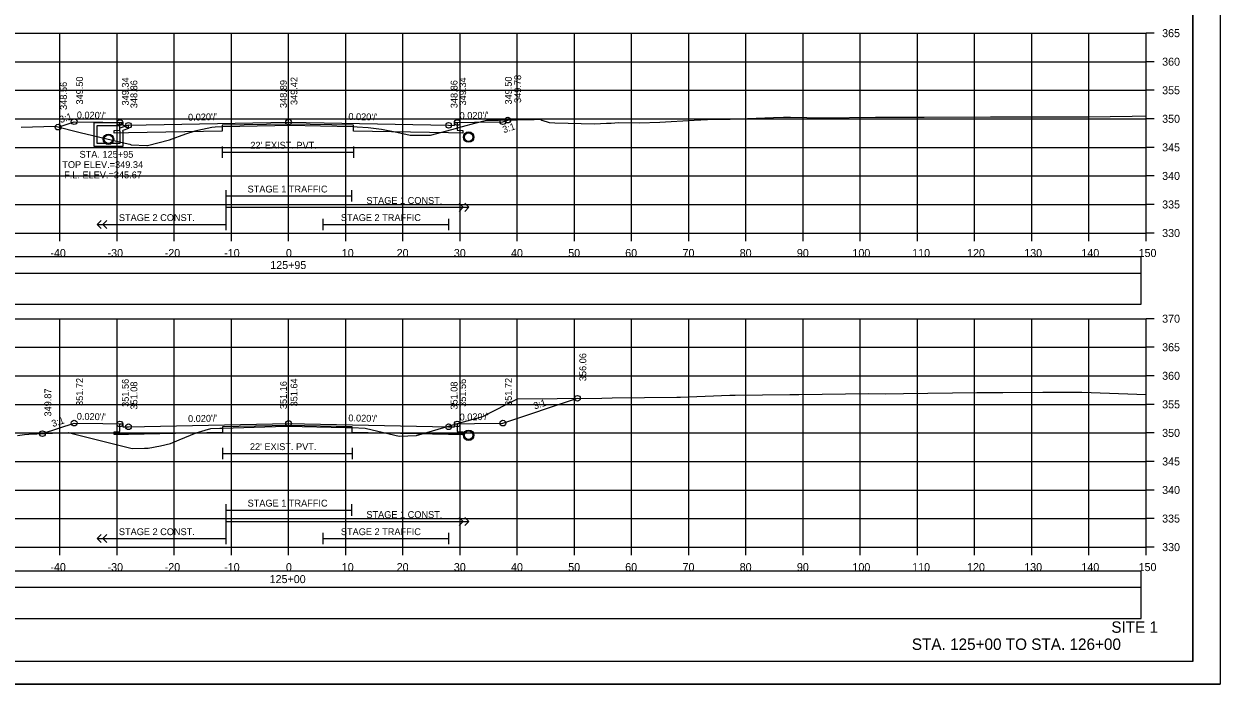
# Model space of a CAD drawing. Extents: x 1368122 to 1710785, y 373130 to 557566.
# Drawn here: x 1368642.6 to 1368851.8, y 376543.7 to 376659.3 of the extents above; entities that cross this region are included whole.
import ezdxf

# ---------------------------------------------------------------- set-up
doc = ezdxf.new("R2010")
doc.units = 0
for name, color, linetype in [('R_Alt Surface', 7, 'Continuous'), ('R_Axis', 7, 'Continuous'), ('R_Axis Annot', 7, 'Continuous'), ('R_Border', 7, 'Continuous'), ('R_Draft', 7, 'Continuous'), ('R_Exist Surface', 7, 'Continuous'), ('R_Fin Surface', 7, 'Continuous'), ('R_Grid', 7, 'Continuous'), ('R_No Plot', 7, 'Continuous'), ('R_Striping', 7, 'Continuous'), ('R_Water', 7, 'Continuous'), ('R_Water Annot', 7, 'Continuous'), ('R_Xsect Elev', 7, 'Continuous'), ('R_Xsect Slope', 7, 'Continuous')]:
    doc.layers.add(name, color=color, linetype=linetype)

msp = doc.modelspace()

# ---------------------------------------------------------------- linework, layer by layer
for points in [[(1368539.73, 376610.24), (1368838.03, 376610.24), (1368838.03, 376615.65), (1368539.73, 376615.65)], [(1368539.73, 376555.24), (1368838.03, 376555.24), (1368838.03, 376560.65), (1368539.73, 376560.65)]]:
    msp.add_lwpolyline(points, close=True)
at = {"layer": 'R_Alt Surface'}
for points in [[(1368718.38, 376642.06), (1368718.38, 376640.72), (1368719.38, 376640.7), (1368719.38, 376640.2), (1368716.88, 376640.25), (1368700.23, 376640.58), (1368700.23, 376641.58), (1368688.88, 376641.81), (1368677.25, 376641.58), (1368677.25, 376640.58), (1368660.88, 376640.25), (1368658.38, 376640.2), (1368658.38, 376640.7), (1368659.38, 376640.72), (1368659.38, 376642.06)], [(1368677.25, 376637.89), (1368677.25, 376635.89)], [(1368677.25, 376636.89), (1368700.23, 376636.89)], [(1368700.23, 376637.89), (1368700.23, 376635.89)], [(1368718.38, 376589.28), (1368718.38, 376587.94), (1368719.38, 376587.92), (1368719.38, 376587.42), (1368716.88, 376587.47), (1368699.98, 376587.81), (1368699.98, 376588.81), (1368688.88, 376589.03), (1368677.35, 376588.8), (1368677.35, 376587.8), (1368660.88, 376587.47), (1368658.38, 376587.42), (1368658.38, 376587.92), (1368659.38, 376587.94), (1368659.38, 376589.28)], [(1368677.35, 376585.11), (1368677.35, 376583.11)], [(1368677.35, 376584.11), (1368699.98, 376584.11)], [(1368699.98, 376585.11), (1368699.98, 376583.11)]]:
    msp.add_lwpolyline(points, dxfattribs=at)
for points in [[(1368539.73, 376615.71), (1368838.03, 376615.71), (1368838.03, 376618.53), (1368539.73, 376618.53)], [(1368539.73, 376560.71), (1368838.03, 376560.71), (1368838.03, 376563.53), (1368539.73, 376563.53)]]:
    msp.add_lwpolyline(points, close=True, dxfattribs=at)
at = {"layer": 'R_Axis'}
for p, q in [((1368838.88, 376622.72), (1368838.88, 376657.72)), ((1368840.28, 376657.72), (1368838.88, 376657.72)), ((1368840.28, 376652.72), (1368838.88, 376652.72)), ((1368840.28, 376647.72), (1368838.88, 376647.72)), ((1368840.28, 376642.72), (1368838.88, 376642.72)), ((1368840.28, 376637.72), (1368838.88, 376637.72)), ((1368840.28, 376632.72), (1368838.88, 376632.72)), ((1368840.28, 376627.72), (1368838.88, 376627.72)), ((1368538.88, 376622.72), (1368838.88, 376622.72)), ((1368648.88, 376621.32), (1368648.88, 376622.72)), ((1368658.88, 376621.32), (1368658.88, 376622.72)), ((1368668.88, 376621.32), (1368668.88, 376622.72)), ((1368678.88, 376621.32), (1368678.88, 376622.72)), ((1368688.88, 376621.32), (1368688.88, 376622.72)), ((1368698.88, 376621.32), (1368698.88, 376622.72)), ((1368708.88, 376621.32), (1368708.88, 376622.72)), ((1368718.88, 376621.32), (1368718.88, 376622.72)), ((1368728.88, 376621.32), (1368728.88, 376622.72)), ((1368738.88, 376621.32), (1368738.88, 376622.72)), ((1368748.88, 376621.32), (1368748.88, 376622.72)), ((1368758.88, 376621.32), (1368758.88, 376622.72)), ((1368768.88, 376621.32), (1368768.88, 376622.72)), ((1368778.88, 376621.32), (1368778.88, 376622.72)), ((1368788.88, 376621.32), (1368788.88, 376622.72)), ((1368798.88, 376621.32), (1368798.88, 376622.72)), ((1368808.88, 376621.32), (1368808.88, 376622.72)), ((1368818.88, 376621.32), (1368818.88, 376622.72)), ((1368828.88, 376621.32), (1368828.88, 376622.72)), ((1368838.88, 376621.32), (1368838.88, 376622.72)), ((1368840.28, 376622.72), (1368838.88, 376622.72)), ((1368838.88, 376567.72), (1368838.88, 376607.72)), ((1368840.28, 376607.72), (1368838.88, 376607.72)), ((1368840.28, 376602.72), (1368838.88, 376602.72)), ((1368840.28, 376597.72), (1368838.88, 376597.72)), ((1368840.28, 376592.72), (1368838.88, 376592.72)), ((1368840.28, 376587.72), (1368838.88, 376587.72)), ((1368840.28, 376582.72), (1368838.88, 376582.72)), ((1368840.28, 376577.72), (1368838.88, 376577.72)), ((1368840.28, 376572.72), (1368838.88, 376572.72)), ((1368538.88, 376567.72), (1368838.88, 376567.72)), ((1368648.88, 376566.32), (1368648.88, 376567.72)), ((1368658.88, 376566.32), (1368658.88, 376567.72)), ((1368668.88, 376566.32), (1368668.88, 376567.72)), ((1368678.88, 376566.32), (1368678.88, 376567.72)), ((1368688.88, 376566.32), (1368688.88, 376567.72)), ((1368698.88, 376566.32), (1368698.88, 376567.72)), ((1368708.88, 376566.32), (1368708.88, 376567.72)), ((1368718.88, 376566.32), (1368718.88, 376567.72)), ((1368728.88, 376566.32), (1368728.88, 376567.72)), ((1368738.88, 376566.32), (1368738.88, 376567.72)), ((1368748.88, 376566.32), (1368748.88, 376567.72)), ((1368758.88, 376566.32), (1368758.88, 376567.72)), ((1368768.88, 376566.32), (1368768.88, 376567.72)), ((1368778.88, 376566.32), (1368778.88, 376567.72)), ((1368788.88, 376566.32), (1368788.88, 376567.72)), ((1368798.88, 376566.32), (1368798.88, 376567.72)), ((1368808.88, 376566.32), (1368808.88, 376567.72)), ((1368818.88, 376566.32), (1368818.88, 376567.72)), ((1368828.88, 376566.32), (1368828.88, 376567.72)), ((1368838.88, 376566.32), (1368838.88, 376567.72)), ((1368840.28, 376567.72), (1368838.88, 376567.72))]:
    msp.add_line(p, q, dxfattribs=at)
at = {"layer": 'R_Border'}
for q in [(1368847.06, 376753.18), (1368530.88, 376547.72)]:
    msp.add_line((1368847.06, 376547.72), q, dxfattribs=at)
at = {"layer": 'R_Exist Surface'}
for points in [[(1368642.11, 376641.27), (1368648.03, 376641.41), (1368652.41, 376640.34), (1368658.08, 376638.98), (1368659.79, 376638.59), (1368661.14, 376638.29), (1368661.33, 376638.18), (1368664.06, 376638.03), (1368664.09, 376638.03), (1368664.18, 376638.05), (1368668.03, 376639.03), (1368670.93, 376640.08), (1368672.52, 376640.63), (1368673, 376640.74), (1368675.43, 376641.28), (1368676.07, 376641.3), (1368677.25, 376641.36), (1368686.48, 376641.55), (1368689.06, 376641.61), (1368694.48, 376641.48), (1368700.23, 376641.36), (1368700.87, 376641.33), (1368702.79, 376641.21), (1368703.75, 376641.09), (1368705.13, 376640.91), (1368707.81, 376640.37), (1368710.16, 376639.86), (1368710.23, 376639.86), (1368710.38, 376639.86), (1368711.97, 376639.88), (1368713.68, 376639.87), (1368717.46, 376640.85), (1368719.28, 376641.38), (1368721.48, 376641.94), (1368723.48, 376642.5), (1368725.58, 376642.46), (1368731.85, 376642.59), (1368732.94, 376642.63), (1368733.16, 376642.48), (1368734.49, 376642.06), (1368735.44, 376642.02), (1368742.41, 376641.82), (1368744.49, 376641.97), (1368745.33, 376641.94), (1368746.59, 376642.06), (1368750.26, 376642.04), (1368753.81, 376642.14), (1368759.82, 376642.48), (1368763.35, 376642.68), (1368766.15, 376642.64), (1368773.68, 376642.97), (1368775.43, 376642.99), (1368776.65, 376643.03), (1368782.37, 376642.92), (1368791.55, 376643.01), (1368793.32, 376642.99), (1368800.03, 376643.02), (1368811.65, 376643.06), (1368812.71, 376643.08), (1368825.5, 376643.06), (1368828.72, 376643.08), (1368836.45, 376643.17), (1368838.88, 376643.25)], [(1368641.44, 376587.27), (1368642.71, 376587.46), (1368643.44, 376587.48), (1368650.38, 376587.79), (1368651.48, 376587.51), (1368661.51, 376585), (1368663.66, 376585.03), (1368664.31, 376585.03), (1368666.5, 376585.48), (1368668.23, 376585.85), (1368669.72, 376586.5), (1368672.71, 376587.75), (1368674.29, 376588.2), (1368675.28, 376588.49), (1368676.84, 376588.54), (1368677.35, 376588.56), (1368686.62, 376588.82), (1368688.73, 376588.88), (1368698.86, 376588.69), (1368699.98, 376588.67), (1368702.28, 376588.53), (1368702.49, 376588.52), (1368708.2, 376587.13), (1368708.22, 376587.13), (1368708.22, 376587.13), (1368708.25, 376587.13), (1368711.26, 376587.27), (1368711.64, 376587.38), (1368718.42, 376589.35), (1368722.85, 376590.61), (1368727.04, 376592.77), (1368728.95, 376593.69), (1368735.87, 376593.74), (1368743.66, 376593.83), (1368745.47, 376593.86), (1368756.77, 376593.98), (1368757.44, 376594), (1368766.09, 376594.32), (1368767, 376594.34), (1368776.57, 376594.43), (1368778.15, 376594.45), (1368790.38, 376594.61), (1368793.37, 376594.58), (1368796.43, 376594.61), (1368809.26, 376594.77), (1368813.8, 376594.79), (1368820.79, 376594.83), (1368827.66, 376594.83), (1368838.88, 376594.45)]]:
    msp.add_lwpolyline(points, dxfattribs=at)
for centre in [(1368720.38, 376639.52), (1368720.38, 376587.31)]:
    msp.add_circle(centre, 0.917, dxfattribs=at)
at = {"layer": 'R_Fin Surface'}
for points in [[(1368648.56, 376641.28), (1368651.38, 376642.22), (1368656.38, 376642.12), (1368659.38, 376642.06), (1368659.88, 376642.06), (1368659.88, 376641.56), (1368660.88, 376641.58), (1368688.88, 376642.14), (1368716.88, 376641.58), (1368717.88, 376641.56), (1368717.88, 376642.06), (1368718.38, 376642.06), (1368721.38, 376642.12), (1368726.38, 376642.22), (1368727.21, 376642.5)], [(1368645.83, 376587.59), (1368651.38, 376589.44), (1368656.38, 376589.34), (1368659.38, 376589.28), (1368659.88, 376589.28), (1368659.88, 376588.78), (1368660.88, 376588.8), (1368688.88, 376589.36), (1368716.88, 376588.8), (1368717.88, 376588.78), (1368717.88, 376589.28), (1368718.38, 376589.28), (1368721.38, 376589.34), (1368726.38, 376589.44), (1368739.4, 376593.78)]]:
    msp.add_lwpolyline(points, dxfattribs=at)
at = {"layer": 'R_Grid'}
for p, q in [((1368538.88, 376657.72), (1368838.88, 376657.72)), ((1368648.88, 376622.72), (1368648.88, 376657.72)), ((1368658.88, 376622.72), (1368658.88, 376657.72)), ((1368668.88, 376622.72), (1368668.88, 376657.72)), ((1368678.88, 376622.72), (1368678.88, 376657.72)), ((1368688.88, 376622.72), (1368688.88, 376657.72)), ((1368698.88, 376622.72), (1368698.88, 376657.72)), ((1368708.88, 376622.72), (1368708.88, 376657.72)), ((1368718.88, 376622.72), (1368718.88, 376657.72)), ((1368728.88, 376622.72), (1368728.88, 376657.72)), ((1368738.88, 376622.72), (1368738.88, 376657.72)), ((1368748.88, 376622.72), (1368748.88, 376657.72)), ((1368758.88, 376622.72), (1368758.88, 376657.72)), ((1368768.88, 376622.72), (1368768.88, 376657.72)), ((1368778.88, 376622.72), (1368778.88, 376657.72)), ((1368788.88, 376622.72), (1368788.88, 376657.72)), ((1368798.88, 376622.72), (1368798.88, 376657.72)), ((1368808.88, 376622.72), (1368808.88, 376657.72)), ((1368818.88, 376622.72), (1368818.88, 376657.72)), ((1368828.88, 376622.72), (1368828.88, 376657.72)), ((1368838.88, 376622.72), (1368838.88, 376657.72)), ((1368538.88, 376652.72), (1368838.88, 376652.72)), ((1368538.88, 376647.72), (1368838.88, 376647.72)), ((1368538.88, 376642.72), (1368838.88, 376642.72)), ((1368538.88, 376637.72), (1368838.88, 376637.72)), ((1368538.88, 376632.72), (1368838.88, 376632.72)), ((1368538.88, 376627.72), (1368838.88, 376627.72)), ((1368538.88, 376622.72), (1368838.88, 376622.72)), ((1368538.88, 376607.72), (1368838.88, 376607.72)), ((1368648.88, 376567.72), (1368648.88, 376607.72)), ((1368658.88, 376567.72), (1368658.88, 376607.72)), ((1368668.88, 376567.72), (1368668.88, 376607.72)), ((1368678.88, 376567.72), (1368678.88, 376607.72)), ((1368688.88, 376567.72), (1368688.88, 376607.72)), ((1368698.88, 376567.72), (1368698.88, 376607.72)), ((1368708.88, 376567.72), (1368708.88, 376607.72)), ((1368718.88, 376567.72), (1368718.88, 376607.72)), ((1368728.88, 376567.72), (1368728.88, 376607.72)), ((1368738.88, 376567.72), (1368738.88, 376607.72)), ((1368748.88, 376567.72), (1368748.88, 376607.72)), ((1368758.88, 376567.72), (1368758.88, 376607.72)), ((1368768.88, 376567.72), (1368768.88, 376607.72)), ((1368778.88, 376567.72), (1368778.88, 376607.72)), ((1368788.88, 376567.72), (1368788.88, 376607.72)), ((1368798.88, 376567.72), (1368798.88, 376607.72)), ((1368808.88, 376567.72), (1368808.88, 376607.72)), ((1368818.88, 376567.72), (1368818.88, 376607.72)), ((1368828.88, 376567.72), (1368828.88, 376607.72)), ((1368838.88, 376567.72), (1368838.88, 376607.72)), ((1368538.88, 376602.72), (1368838.88, 376602.72)), ((1368538.88, 376597.72), (1368838.88, 376597.72)), ((1368538.88, 376592.72), (1368838.88, 376592.72)), ((1368538.88, 376587.72), (1368838.88, 376587.72)), ((1368538.88, 376582.72), (1368838.88, 376582.72)), ((1368538.88, 376577.72), (1368838.88, 376577.72)), ((1368538.88, 376572.72), (1368838.88, 376572.72)), ((1368538.88, 376567.72), (1368838.88, 376567.72))]:
    msp.add_line(p, q, dxfattribs=at)
at = {"layer": 'R_No Plot'}
msp.add_line((1368518.48, 376543.74), (1368851.81, 376543.74), dxfattribs=at)
for points in [[(1368518.47, 376757.07), (1368851.81, 376757.07), (1368851.81, 376543.73), (1368518.47, 376543.73)], [(1368764.8, 376753.18), (1368784.42, 376753.18), (1368784.42, 376743.3), (1368800.53, 376743.3), (1368823.73, 376743.3), (1368823.85, 376715.14), (1368847.06, 376715.14), (1368847.06, 376547.72), (1368530.88, 376547.72), (1368530.88, 376753.18)]]:
    msp.add_lwpolyline(points, close=True, dxfattribs=at)
for centre, radius in [((1368651.38, 376642.22), 0.5), ((1368688.88, 376642.14), 0.5), ((1368726.38, 376642.22), 0.5), ((1368727.21, 376642.5), 0.5), ((1368648.56, 376641.28), 0.5), ((1368659.38, 376642.06), 0.5), ((1368660.88, 376641.58), 0.5), ((1368716.88, 376641.58), 0.5), ((1368718.38, 376642.06), 0.5), ((1368657.38, 376639.14), 0.917), ((1368739.4, 376593.78), 0.5), ((1368651.38, 376589.44), 0.5), ((1368659.38, 376589.28), 0.5), ((1368660.88, 376588.8), 0.5), ((1368688.88, 376589.36), 0.5), ((1368716.88, 376588.8), 0.5), ((1368718.38, 376589.28), 0.5), ((1368726.38, 376589.44), 0.5), ((1368645.83, 376587.59), 0.5)]:
    msp.add_circle(centre, radius, dxfattribs=at)
at = {"layer": 'R_Striping'}
for p, q in [((1368719.42, 376627.22), (1368718.71, 376627.92)), ((1368718.71, 376626.51), (1368719.42, 376627.22)), ((1368720.42, 376627.22), (1368719.71, 376627.92)), ((1368719.71, 376626.51), (1368720.42, 376627.22)), ((1368655.38, 376624.22), (1368656.09, 376624.92)), ((1368655.38, 376624.22), (1368677.88, 376624.22)), ((1368656.09, 376623.51), (1368655.38, 376624.22)), ((1368656.38, 376624.22), (1368657.09, 376624.92)), ((1368657.09, 376623.51), (1368656.38, 376624.22)), ((1368719.42, 376572.22), (1368718.71, 376572.92)), ((1368718.71, 376571.51), (1368719.42, 376572.22)), ((1368720.42, 376572.22), (1368719.71, 376572.92)), ((1368719.71, 376571.51), (1368720.42, 376572.22)), ((1368655.38, 376569.22), (1368656.09, 376569.92)), ((1368656.38, 376569.22), (1368657.09, 376569.92)), ((1368655.38, 376569.22), (1368677.88, 376569.22)), ((1368656.09, 376568.51), (1368655.38, 376569.22)), ((1368657.09, 376568.51), (1368656.38, 376569.22))]:
    msp.add_line(p, q, dxfattribs=at)
for points in [[(1368677.88, 376630.22), (1368677.88, 376623.22)], [(1368699.88, 376630.22), (1368699.88, 376628.22)], [(1368677.88, 376629.22), (1368699.88, 376629.22)], [(1368677.88, 376627.22), (1368720.42, 376627.22)], [(1368694.88, 376625.22), (1368694.88, 376623.22)], [(1368694.88, 376624.22), (1368716.88, 376624.22)], [(1368716.88, 376625.22), (1368716.88, 376623.22)], [(1368677.88, 376575.22), (1368677.88, 376568.22)], [(1368677.88, 376574.22), (1368699.88, 376574.22)], [(1368699.88, 376575.22), (1368699.88, 376573.22)], [(1368677.88, 376572.22), (1368720.42, 376572.22)], [(1368694.88, 376570.22), (1368694.88, 376568.22)], [(1368716.88, 376570.22), (1368716.88, 376568.22)], [(1368694.88, 376569.22), (1368716.88, 376569.22)]]:
    msp.add_lwpolyline(points, dxfattribs=at)
at = {"layer": 'R_Water'}
for p, q in [((1368654.88, 376642.06), (1368659.63, 376642.06)), ((1368654.88, 376640.56), (1368654.88, 376642.06)), ((1368655.38, 376640.56), (1368655.38, 376641.56)), ((1368655.38, 376641.56), (1368659.38, 376641.56)), ((1368659.71, 376641.89), (1368659.38, 376641.56)), ((1368660.88, 376641.58), (1368659.38, 376641.06)), ((1368659.38, 376640.56), (1368659.38, 376641.06)), ((1368659.71, 376641.89), (1368659.63, 376642.06)), ((1368660.88, 376641.05), (1368659.88, 376640.7)), ((1368659.88, 376640.56), (1368659.88, 376640.7))]:
    msp.add_line(p, q, dxfattribs=at)
for points in [[(1368659.88, 376640.56), (1368659.88, 376637.89), (1368657.38, 376637.89), (1368654.88, 376637.89), (1368654.88, 376640.56)], [(1368659.38, 376640.56), (1368659.38, 376638.39), (1368657.38, 376638.39), (1368655.38, 376638.39), (1368655.38, 376640.56)], [(1368660.88, 376641.05), (1368660.88, 376641.58)]]:
    msp.add_lwpolyline(points, dxfattribs=at)
for centre in [(1368657.38, 376639.14), (1368720.38, 376639.52), (1368720.38, 376587.31)]:
    msp.add_circle(centre, 0.75, dxfattribs=at)
at = {"layer": 'R_Xsect Elev'}
for p, q in [((1368688.88, 376641.61), (1368688.88, 376651.61)), ((1368688.88, 376588.88), (1368688.88, 376598.88))]:
    msp.add_line(p, q, dxfattribs=at)

# ---------------------------------------------------------------- texts
at = {"layer": 'R_Axis Annot'}
for s, p in [('365', (1368841.68, 376657.02)), ('360', (1368841.68, 376652.02)), ('355', (1368841.68, 376647.02)), ('350', (1368841.68, 376642.02)), ('345', (1368841.68, 376637.02)), ('340', (1368841.68, 376632.02)), ('335', (1368841.68, 376627.02)), ('330', (1368841.68, 376622.02)), ('-40', (1368647.22, 376618.52)), ('-30', (1368657.22, 376618.52)), ('-20', (1368667.22, 376618.52)), ('-10', (1368677.62, 376618.52)), ('0', (1368688.42, 376618.52)), ('10', (1368698.19, 376618.52)), ('20', (1368707.79, 376618.52)), ('30', (1368717.79, 376618.52)), ('40', (1368727.79, 376618.52)), ('50', (1368737.79, 376618.52)), ('60', (1368747.76, 376618.52)), ('70', (1368757.79, 376618.52)), ('80', (1368767.79, 376618.52)), ('90', (1368777.79, 376618.52)), ('100', (1368787.51, 376618.52)), ('110', (1368797.96, 376618.52)), ('120', (1368807.56, 376618.52)), ('130', (1368817.56, 376618.52)), ('140', (1368827.56, 376618.52)), ('150', (1368837.56, 376618.52)), ('125+95', (1368685.68, 376616.42)), ('370', (1368841.68, 376607.02)), ('365', (1368841.68, 376602.02)), ('360', (1368841.68, 376597.02)), ('355', (1368841.68, 376592.02)), ('350', (1368841.68, 376587.02)), ('345', (1368841.68, 376582.02)), ('340', (1368841.68, 376577.02)), ('335', (1368841.68, 376572.02)), ('330', (1368841.68, 376567.02)), ('-40', (1368647.22, 376563.52)), ('-30', (1368657.22, 376563.52)), ('-20', (1368667.22, 376563.52)), ('-10', (1368677.62, 376563.52)), ('0', (1368688.42, 376563.52)), ('10', (1368698.19, 376563.52)), ('20', (1368707.79, 376563.52)), ('30', (1368717.79, 376563.52)), ('40', (1368727.79, 376563.52)), ('50', (1368737.79, 376563.52)), ('60', (1368747.76, 376563.52)), ('70', (1368757.79, 376563.52)), ('80', (1368767.79, 376563.52)), ('90', (1368777.79, 376563.52)), ('100', (1368787.51, 376563.52)), ('110', (1368797.96, 376563.52)), ('120', (1368807.56, 376563.52)), ('130', (1368817.56, 376563.52)), ('140', (1368827.56, 376563.52)), ('150', (1368837.56, 376563.52)), ('125+00', (1368685.57, 376561.42))]:
    msp.add_text(s, height=1.4, dxfattribs=at).set_placement(p)
at = {"layer": 'R_Draft'}
for s, p in [('SITE 1', (1368832.79, 376552.72)), ('STA. 125+00 TO STA. 126+00', (1368797.9, 376549.72))]:
    msp.add_text(s, height=2, dxfattribs=at).set_placement(p)
at = {"layer": 'R_Striping'}
for s, p in [('STAGE 1 TRAFFIC', (1368681.71, 376629.82)), ('STAGE 1 CONST.', (1368702.49, 376627.82)), ('STAGE 2 CONST.', (1368659.2, 376624.82)), ('STAGE 2 TRAFFIC', (1368698.03, 376624.82)), ('STAGE 1 TRAFFIC', (1368681.71, 376574.82)), ('STAGE 1 CONST.', (1368702.49, 376572.82)), ('STAGE 2 CONST.', (1368659.2, 376569.82)), ('STAGE 2 TRAFFIC', (1368698.03, 376569.82))]:
    msp.add_text(s, height=1.2, dxfattribs=at).set_placement(p)
at = {"layer": 'R_Water'}
for p in [(1368682.19, 376637.49), (1368682.12, 376584.71)]:
    msp.add_text("22' EXIST. PVT.", height=1.2, dxfattribs=at).set_placement(p)
at = {"layer": 'R_Water Annot'}
for s, p in [('STA. 125+95', (1368652.32, 376635.9)), ('TOP ELEV.=349.34', (1368649.3, 376634.1)), ('F.L. ELEV.=345.67', (1368649.62, 376632.3))]:
    msp.add_text(s, height=1.2, dxfattribs=at).set_placement(p)
at = {"layer": 'R_Xsect Elev'}
for s, p in [('348.56', (1368650.11, 376644.28)), ('349.50', (1368652.93, 376645.22)), ('349.34', (1368660.93, 376645.06)), ('348.86', (1368662.43, 376644.58)), ('348.89', (1368688.58, 376644.61)), ('349.42', (1368690.43, 376645.14)), ('348.86', (1368718.43, 376644.58)), ('349.34', (1368719.93, 376645.06)), ('349.50', (1368727.93, 376645.22)), ('349.78', (1368729.56, 376645.5)), ('356.06', (1368740.95, 376596.78)), ('351.72', (1368652.93, 376592.44)), ('351.56', (1368660.93, 376592.28)), ('351.08', (1368662.43, 376591.8)), ('351.16', (1368688.58, 376591.88)), ('351.64', (1368690.43, 376592.36)), ('351.08', (1368718.43, 376591.8)), ('351.56', (1368719.93, 376592.28)), ('351.72', (1368727.93, 376592.44)), ('349.87', (1368647.38, 376590.59))]:
    msp.add_text(s, height=1.2, rotation=90, dxfattribs=at).set_placement(p)
at = {"layer": 'R_Xsect Slope'}
for s, rotation, p in [('3:1', 18.4349, (1368649.02, 376641.96)), ("0.020'/'", 358.8542, (1368651.83, 376642.81)), ("0.020'/'", 1.1458, (1368671.31, 376642.39)), ("0.020'/'", 358.8542, (1368699.33, 376642.53)), ("0.020'/'", 1.1458, (1368718.81, 376642.67)), ('3:1', 18.4349, (1368726.53, 376640.2)), ('3:1', 18.4349, (1368731.94, 376591.82)), ('3:1', 18.4349, (1368647.66, 376588.73)), ("0.020'/'", 358.8542, (1368651.83, 376590.03)), ("0.020'/'", 1.1458, (1368671.31, 376589.61)), ("0.020'/'", 358.8542, (1368699.33, 376589.75)), ("0.020'/'", 1.1458, (1368718.81, 376589.89))]:
    msp.add_text(s, height=1.2, rotation=rotation, dxfattribs=at).set_placement(p)

doc.saveas('drawing.dxf')
